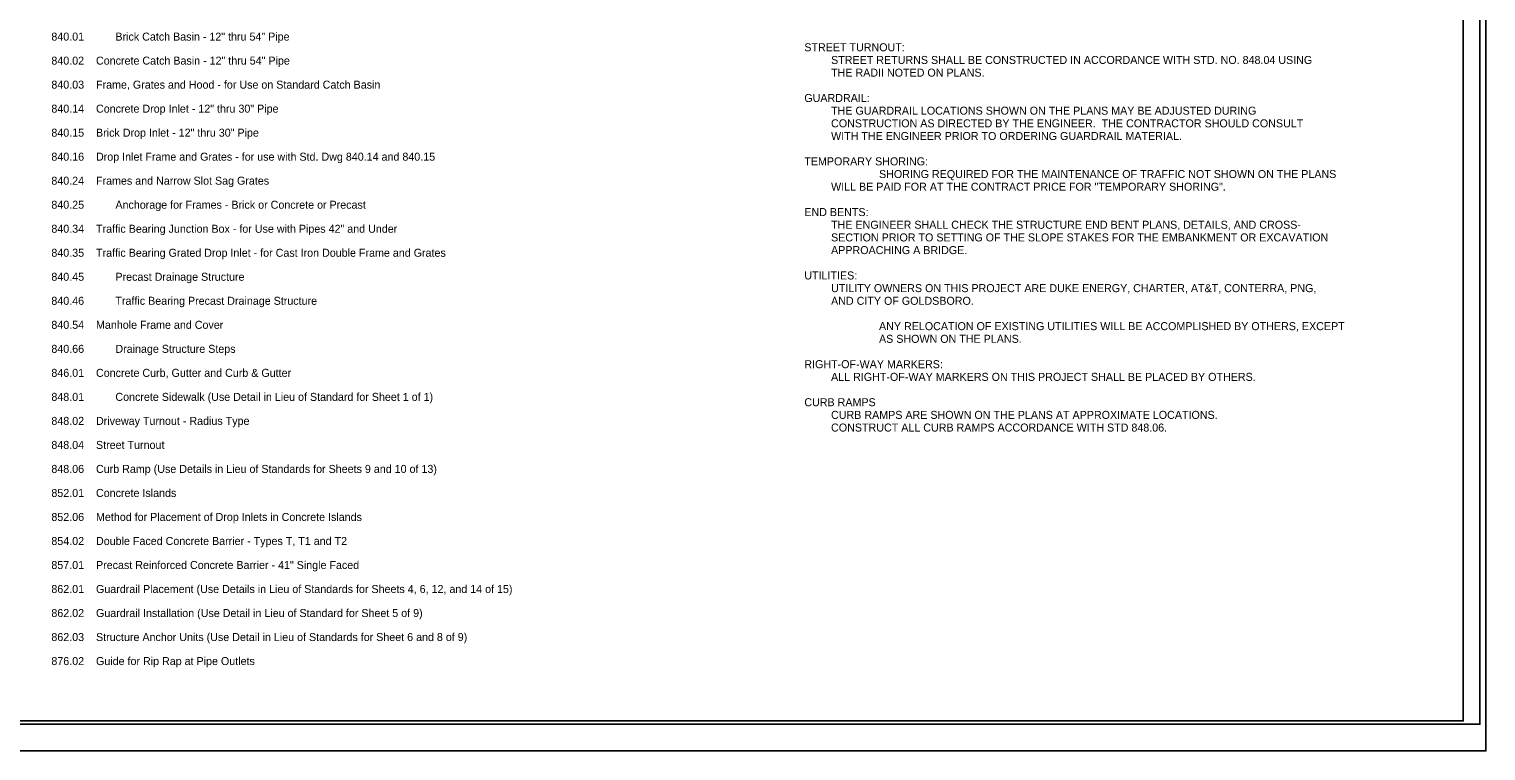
# Model space of a CAD drawing. Extents: x 775818 to 777502, y 889228 to 890323.
# Drawn here: x 776410 to 777502, y 889228 to 889769 of the extents above; entities that cross this region are included whole.
import ezdxf

# ---------------------------------------------------------------- set-up
doc = ezdxf.new("R2010")
doc.units = 0
for name, color, linetype in [('Sheet Cutting Line CELL', 7, 'Continuous'), ('Sheet Data Text CELL', 7, 'Continuous'), ('Sheet Plan CELL', 7, 'Continuous'), ('Sheet Plot Border Inside CELL', 7, 'Continuous'), ('Sheet Plot Border Outside CELL', 7, 'Continuous')]:
    doc.layers.add(name, color=color, linetype=linetype)

msp = doc.modelspace()

# ---------------------------------------------------------------- linework, layer by layer
at = {"layer": 'Sheet Cutting Line CELL'}
msp.add_line((775818.3, 889228.3), (777501.8, 889228.3), dxfattribs=at)
at = {"layer": 'Sheet Plan CELL'}
msp.add_lwpolyline([(777484.8, 890300.8), (775984.8, 890300.8), (775984.8, 889250.8), (777484.8, 889250.8)], close=True, dxfattribs=at)
at = {"layer": 'Sheet Plot Border Inside CELL'}
msp.add_lwpolyline([(775831.3, 889248.3), (777497.3, 889248.3), (777497.3, 890303.3), (775831.3, 890303.3)], close=True, dxfattribs=at)
at = {"layer": 'Sheet Plot Border Outside CELL'}
msp.add_lwpolyline([(775818.3, 889228.3), (777501.8, 889228.3), (777501.8, 890323.3), (775818.3, 890323.3)], close=True, dxfattribs=at)

# ---------------------------------------------------------------- texts
at = {"layer": 'Sheet Data Text CELL'}
for s, p in [('840.01    ', (776426.5, 889760.6)), ('Brick Catch Basin - 12" thru 54" Pipe', (776474.5, 889760.6)), ('STREET TURNOUT:  ', (776990.9, 889752.6)), ('840.02    Concrete Catch Basin - 12" thru 54" Pipe', (776426.5, 889742.6)), ('         STREET RETURNS SHALL BE CONSTRUCTED IN ACCORDANCE WITH STD. NO. 848.04 USING ', (776990.9, 889743.1)), ('840.03    Frame, Grates and Hood - for Use on Standard Catch Basin', (776426.5, 889724.6)), ('         THE RADII NOTED ON PLANS.  ', (776990.9, 889733.6)), ('GUARDRAIL:  ', (776990.9, 889714.6)), ('840.14    Concrete Drop Inlet - 12" thru 30" Pipe', (776426.5, 889706.6)), ('         THE GUARDRAIL LOCATIONS SHOWN ON THE PLANS MAY BE ADJUSTED DURING', (776990.9, 889705.1)), ('         CONSTRUCTION AS DIRECTED BY THE ENGINEER.  THE CONTRACTOR SHOULD CONSULT', (776990.9, 889695.6)), ('840.15    Brick Drop Inlet - 12" thru 30" Pipe', (776426.5, 889688.6)), ('         WITH THE ENGINEER PRIOR TO ORDERING GUARDRAIL MATERIAL.', (776990.9, 889686.1)), ('840.16    Drop Inlet Frame and Grates - for use with Std. Dwg 840.14 and 840.15', (776426.5, 889670.6)), ('TEMPORARY SHORING:', (776990.9, 889667.1)), ('840.24    Frames and Narrow Slot Sag Grates', (776426.5, 889652.6)), ('SHORING REQUIRED FOR THE MAINTENANCE OF TRAFFIC NOT SHOWN ON THE PLANS ', (777046.9, 889657.6)), ('         WILL BE PAID FOR AT THE CONTRACT PRICE FOR "TEMPORARY SHORING".', (776990.9, 889648.1)), ('840.25', (776426.5, 889634.6)), ('Anchorage for Frames - Brick or Concrete or Precast', (776474.5, 889634.6)), ('END BENTS:  ', (776990.9, 889629.1)), ('840.34    Traffic Bearing Junction Box - for Use with Pipes 42" and Under', (776426.5, 889616.6)), ('         THE ENGINEER SHALL CHECK THE STRUCTURE END BENT PLANS, DETAILS, AND CROSS-', (776990.9, 889619.6)), ('         SECTION PRIOR TO SETTING OF THE SLOPE STAKES FOR THE EMBANKMENT OR EXCAVATION ', (776990.9, 889610.1)), ('840.35    Traffic Bearing Grated Drop Inlet - for Cast Iron Double Frame and Grates', (776426.5, 889598.6)), ('         APPROACHING A BRIDGE.  ', (776990.9, 889600.6)), ('840.45', (776426.5, 889580.6)), ('Precast Drainage Structure', (776474.5, 889580.6)), ('UTILITIES:  ', (776990.9, 889581.6)), ('         UTILITY OWNERS ON THIS PROJECT ARE DUKE ENERGY, CHARTER, AT&T, CONTERRA, PNG,', (776990.9, 889572.1)), ('840.46', (776426.5, 889562.6)), ('Traffic Bearing Precast Drainage Structure', (776474.5, 889562.6)), ('         AND CITY OF GOLDSBORO.', (776990.9, 889562.6)), ('840.54    Manhole Frame and Cover', (776426.5, 889544.6)), ('ANY RELOCATION OF EXISTING UTILITIES WILL BE ACCOMPLISHED BY OTHERS, EXCEPT', (777046.9, 889543.6)), ('AS SHOWN ON THE PLANS.', (777046.9, 889534.1)), ('840.66', (776426.5, 889526.6)), ('Drainage Structure Steps', (776474.5, 889526.6)), ('846.01    Concrete Curb, Gutter and Curb & Gutter', (776426.5, 889508.6)), ('RIGHT-OF-WAY MARKERS:  ', (776990.9, 889515.1)), ('         ALL RIGHT-OF-WAY MARKERS ON THIS PROJECT SHALL BE PLACED BY OTHERS. ', (776990.9, 889505.6)), ('848.01', (776426.5, 889490.6)), ('Concrete Sidewalk (Use Detail in Lieu of Standard for Sheet 1 of 1)', (776474.5, 889490.6)), ('CURB RAMPS', (776990.9, 889486.6)), ('         CURB RAMPS ARE SHOWN ON THE PLANS AT APPROXIMATE LOCATIONS.', (776990.9, 889477.1)), ('848.02    Driveway Turnout - Radius Type', (776426.5, 889472.6)), ('         CONSTRUCT ALL CURB RAMPS ACCORDANCE WITH STD 848.06.', (776990.9, 889467.6)), ('848.04    Street Turnout', (776426.5, 889454.6)), ('848.06    Curb Ramp (Use Details in Lieu of Standards for Sheets 9 and 10 of 13)', (776426.5, 889436.6)), ('852.01    Concrete Islands', (776426.5, 889418.6)), ('852.06    Method for Placement of Drop Inlets in Concrete Islands', (776426.5, 889400.6)), ('854.02    Double Faced Concrete Barrier - Types T, T1 and T2', (776426.5, 889382.6)), ('857.01    Precast Reinforced Concrete Barrier - 41" Single Faced', (776426.5, 889364.6)), ('862.01    Guardrail Placement (Use Details in Lieu of Standards for Sheets 4, 6, 12, and 14 of 15)', (776426.5, 889346.6)), ('862.02    Guardrail Installation (Use Detail in Lieu of Standard for Sheet 5 of 9)', (776426.5, 889328.6)), ('862.03    Structure Anchor Units (Use Detail in Lieu of Standards for Sheet 6 and 8 of 9)', (776426.5, 889310.6)), ('876.02    Guide for Rip Rap at Pipe Outlets', (776426.5, 889292.6))]:
    msp.add_text(s, height=6, dxfattribs=at).set_placement(p)

doc.saveas('drawing.dxf')
